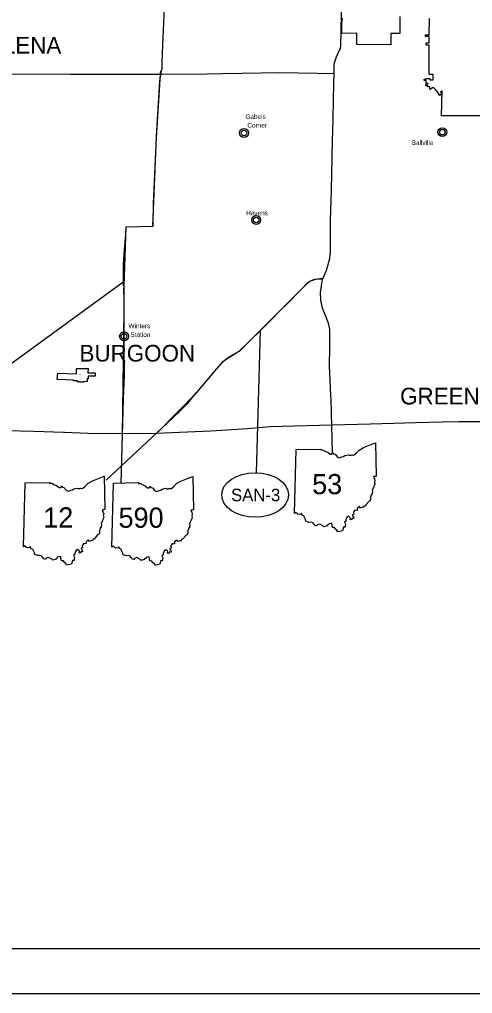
# Model space of a CAD drawing. Extents: x 0 to 798, y 0 to 440.
# Drawn here: x 266.6 to 368.1, y 0 to 218.5 of the extents above; entities that cross this region are included whole.
import ezdxf

# ---------------------------------------------------------------- set-up
doc = ezdxf.new("R2010")
doc.units = 0
for name, color, linetype in [('DV_X_Corp_Line', 7, 'Continuous'), ('GM_X_Corporation_Text', 7, 'Continuous'), ('GM_X_County', 7, 'Continuous'), ('GM_X_Rail_Line', 7, 'Continuous'), ('GM_X_State_Route', 7, 'Continuous'), ('GM_X_US_Route', 7, 'Continuous'), ('PV_P_Text', 7, 'Continuous'), ('SH_Border', 7, 'Continuous'), ('SH_Cut_Line', 7, 'Continuous'), ('SH_Data', 7, 'Continuous'), ('SH_Text', 7, 'Continuous')]:
    doc.layers.add(name, color=color, linetype=linetype)

msp = doc.modelspace()

# ---------------------------------------------------------------- linework, layer by layer
at = {"layer": 'DV_X_Corp_Line'}
for points in [[(351.89, 219.21), (351.83, 215.37), (349.85, 215.38), (349.85, 212.82), (342.22, 212.93), (342.22, 215.43), (338.88, 215.38), (338.88, 217.79), (338.97, 218.79)], [(376.75, 196.87), (366.34, 196.86), (361.22, 196.9), (361.38, 202.52), (360.99, 202.18), (361.27, 201.86), (360.83, 201.46), (360.54, 201.8), (360.61, 201.87), (360.16, 202.41), (359.75, 202.9), (359.44, 203.28), (359.36, 203.3), (359.36, 203.25), (358.57, 202.79), (358.57, 203.37), (358.17, 203.36), (358.17, 203.65), (357.72, 203.64), (357.73, 204.02), (358.21, 204.04), (358.21, 204.17), (357.74, 204.16), (357.75, 204.78), (357.3, 204.79), (357.3, 205.13), (357.76, 205.12), (357.76, 205.25), (358.56, 205.25), (358.57, 204.95), (359.31, 204.96), (359.3, 206.14), (358.45, 206.17), (358.44, 212.72), (357.78, 212.72), (357.78, 213.24), (358.44, 213.24), (358.44, 214.67), (357.62, 214.67), (357.62, 215.07), (358.45, 215.07), (358.48, 218.73)]]:
    msp.add_lwpolyline(points, dxfattribs=at)
msp.add_lwpolyline([(275.17, 139.19), (279.4, 139.03), (279.4, 140.22), (281.95, 140.21), (281.94, 139.27), (283.58, 139.23), (283.56, 138.47), (282.01, 138.5), (282.01, 137.92), (281.78, 137.92), (281.77, 137.24), (280.91, 137.27), (280.92, 137.12), (280.01, 137.14), (280.01, 137.24), (279.59, 137.25), (279.59, 137.43), (278.72, 137.46), (278.71, 137.62), (275.06, 137.72)], close=True, dxfattribs=at)
for centre, radius in [((316.92, 193.04), 0.982), ((316.92, 193.04), 0.623), ((361.39, 193.22), 0.982), ((361.39, 193.22), 0.623), ((319.64, 173.52), 0.982), ((319.64, 173.52), 0.623), ((290.03, 147.43), 0.982), ((290.03, 147.43), 0.623)]:
    msp.add_circle(centre, radius, dxfattribs=at)
at = {"layer": 'GM_X_County'}
msp.add_lwpolyline([(371.53, 128.26), (365.1, 128.22), (361.36, 128.16), (355.34, 128.01), (350.47, 127.86), (345.25, 127.7), (336.59, 127.48), (322.74, 127.1), (317.71, 126.66), (311.9, 126.27), (309.5, 126.13), (297.21, 125.6), (289.69, 125.53), (281.92, 125.62), (276.69, 125.82), (276.46, 125.82), (269.81, 126.07), (263.62, 126.19)], dxfattribs=at)
at = {"layer": 'GM_X_Rail_Line'}
msp.add_lwpolyline([(280.17, 138.87), (280.15, 138.93)], dxfattribs=at)
at = {"layer": 'GM_X_State_Route'}
for points in [[(298.6, 208.69), (298.59, 208.92), (298.76, 212.81), (298.99, 219.43), (299.23, 225.95), (299.47, 232.59), (299.71, 239.18), (300.21, 252.46), (300.21, 252.59)], [(298.19, 206.38), (298.23, 206.64), (298.31, 206.82), (298.45, 207.13), (298.59, 207.47), (298.61, 207.68), (298.6, 208.69)], [(290.12, 138.69), (290.06, 145.16), (290.08, 149.59), (290.07, 152.09), (290.05, 155.62), (290.01, 158), (290.02, 158.52), (290.02, 158.65), (290, 158.71), (289.92, 158.75), (289.93, 161.49), (289.92, 163.48), (290.13, 166.9), (290.4, 170.25), (290.52, 172.02), (296.56, 172.16), (296.64, 177.24), (296.85, 182.12), (297.23, 190.37), (297.31, 192.06), (298.17, 206.25), (298.19, 206.38)], [(336.9, 196.19), (336.91, 196.38), (337.07, 204.29), (337.13, 206.38)], [(336.78, 191.43), (336.83, 193.42), (336.9, 196.19), (336.9, 196.19)], [(335.31, 162.01), (335.4, 162.23), (336.15, 164.88), (336.25, 165.75), (336.28, 165.95), (336.28, 166.97), (336.29, 171.39), (336.34, 173.5), (336.5, 180.16), (336.78, 191.43), (336.78, 191.43)], [(334.58, 160.34), (335.31, 162.01)], [(314.86, 143.53), (315.2, 143.73), (315.67, 144), (316.04, 144.24), (322.79, 150.94), (325.42, 153.58), (326.42, 154.58), (329.83, 158), (331.24, 159.5), (331.49, 159.66), (331.83, 159.85), (332.19, 160.01), (332.43, 160.1)], [(332.43, 160.1), (332.56, 160.14), (333.05, 160.26), (333.4, 160.3), (334.58, 160.34)], [(334.38, 159.41), (334.42, 159.7), (334.58, 160.34)], [(336.74, 121.42), (336.46, 133.25), (336.41, 134.16), (336.12, 140.79), (336.17, 144.93), (336.13, 149.06), (335.83, 150.35), (335.72, 150.79), (334.55, 153.75), (334.16, 155.43), (334.07, 157.33), (334.26, 158.6)], [(334.26, 158.6), (334.38, 159.41)], [(306.35, 134.87), (306.35, 134.87), (307.02, 135.66), (309.28, 138.3), (310.17, 139.37), (311.4, 140.83), (312.14, 141.71), (312.87, 142.34), (314.86, 143.53), (314.86, 143.53)], [(289.41, 114.38), (289.89, 133.47), (290.12, 138.69)], [(304.9, 133.17), (304.91, 133.17), (306.35, 134.87)], [(286.02, 115.16), (299.7, 127.92), (302.36, 130.48), (303.52, 131.6), (303.99, 132.12), (304.31, 132.47), (304.9, 133.17)]]:
    msp.add_lwpolyline(points, dxfattribs=at)
at = {"layer": 'GM_X_US_Route'}
for points in [[(338.69, 215.45), (338.78, 220.46), (338.8, 221.88), (338.81, 222.12), (338.91, 222.56), (339.02, 222.9), (339.12, 223.18), (339.36, 223.69), (339.81, 224.46), (340.92, 226.41), (341.2, 226.85)], [(337.68, 210.11), (338.43, 211.78), (338.55, 212.03), (338.59, 212.11), (338.64, 212.55), (338.65, 212.94), (338.69, 215.41), (338.69, 215.45)], [(337.13, 206.38), (337.16, 207.08), (337.17, 208.08), (337.24, 208.77), (337.48, 209.68), (337.67, 210.1), (337.68, 210.11)], [(264.97, 206.33), (277.99, 206.24), (282.04, 206.26), (287.96, 206.21)], [(287.96, 206.21), (288.09, 206.21), (297.91, 206.24)], [(297.91, 206.24), (298.17, 206.25), (298.53, 206.24), (308.63, 206.3), (312.16, 206.41), (320.72, 206.57), (324.87, 206.64), (333.34, 206.47), (337.13, 206.38)]]:
    msp.add_lwpolyline(points, dxfattribs=at)
at = {"layer": 'PV_P_Text'}
for p, q in [((328.24, 107.67), (328.64, 122.04)), ((328.24, 107.67), (328.64, 122.04)), ((267.46, 100.2), (267.86, 114.56)), ((267.46, 100.2), (267.86, 114.56)), ((287.29, 100.14), (287.69, 114.5)), ((287.29, 100.14), (287.69, 114.5))]:
    msp.add_line(p, q, dxfattribs=at)
for points in [[(328.64, 122.04), (334.21, 122.13), (334.13, 121.96), (334.65, 121.92), (335.21, 121.61), (335.68, 121.42), (336.26, 120.96), (336.61, 120.97), (336.75, 121.34), (337.02, 121.05), (337.33, 121), (337.87, 120.31), (338.32, 120.17), (338.86, 120.4), (339.26, 120.44), (339.56, 120.67), (340.32, 120.87), (340.53, 120.75), (340.94, 120.78), (341.14, 120.86), (341.5, 120.79), (342.12, 121.31), (342.76, 121.92), (343.74, 122.51), (345.21, 123.06), (346.37, 123.55), (346.54, 116.09)], [(328.64, 122.04), (334.21, 122.13), (334.13, 121.96), (334.65, 121.92), (335.21, 121.61), (335.68, 121.42), (336.26, 120.96), (336.61, 120.97), (336.75, 121.34), (337.02, 121.05), (337.33, 121), (337.87, 120.31), (338.32, 120.17), (338.86, 120.4), (339.26, 120.44), (339.56, 120.67), (340.32, 120.87), (340.53, 120.75), (340.94, 120.78), (341.14, 120.86), (341.5, 120.79), (342.12, 121.31), (342.76, 121.92), (343.74, 122.51), (345.21, 123.06), (346.37, 123.55), (346.54, 116.09)], [(267.86, 114.56), (273.44, 114.66), (273.35, 114.48), (273.87, 114.45), (274.43, 114.14), (274.91, 113.95), (275.48, 113.49), (275.83, 113.5), (275.98, 113.87), (276.24, 113.58), (276.55, 113.53), (277.1, 112.84), (277.55, 112.69), (278.08, 112.93), (278.48, 112.97), (278.78, 113.2), (279.54, 113.4), (279.76, 113.28), (280.16, 113.3), (280.36, 113.39), (280.72, 113.31), (281.34, 113.84), (281.98, 114.45), (282.96, 115.03), (284.43, 115.58), (285.6, 116.08), (285.76, 108.62)], [(267.86, 114.56), (273.44, 114.66), (273.35, 114.48), (273.87, 114.45), (274.43, 114.14), (274.91, 113.95), (275.48, 113.49), (275.83, 113.5), (275.98, 113.87), (276.24, 113.58), (276.55, 113.53), (277.1, 112.84), (277.55, 112.69), (278.08, 112.93), (278.48, 112.97), (278.78, 113.2), (279.54, 113.4), (279.76, 113.28), (280.16, 113.3), (280.36, 113.39), (280.72, 113.31), (281.34, 113.84), (281.98, 114.45), (282.96, 115.03), (284.43, 115.58), (285.6, 116.08), (285.76, 108.62)], [(287.69, 114.5), (293.26, 114.6), (293.18, 114.42), (293.7, 114.39), (294.26, 114.08), (294.73, 113.89), (295.31, 113.43), (295.66, 113.43), (295.8, 113.81), (296.07, 113.52), (296.38, 113.47), (296.92, 112.78), (297.37, 112.63), (297.91, 112.87), (298.31, 112.91), (298.61, 113.14), (299.37, 113.34), (299.58, 113.22), (299.99, 113.24), (300.19, 113.33), (300.55, 113.25), (301.17, 113.77), (301.81, 114.39), (302.79, 114.97), (304.26, 115.52), (305.42, 116.01), (305.59, 108.56)], [(287.69, 114.5), (293.26, 114.6), (293.18, 114.42), (293.7, 114.39), (294.26, 114.08), (294.73, 113.89), (295.31, 113.43), (295.66, 113.43), (295.8, 113.81), (296.07, 113.52), (296.38, 113.47), (296.92, 112.78), (297.37, 112.63), (297.91, 112.87), (298.31, 112.91), (298.61, 113.14), (299.37, 113.34), (299.58, 113.22), (299.99, 113.24), (300.19, 113.33), (300.55, 113.25), (301.17, 113.77), (301.81, 114.39), (302.79, 114.97), (304.26, 115.52), (305.42, 116.01), (305.59, 108.56)], [(346.54, 116.09), (346.37, 115.99), (346.1, 116.04), (345.92, 115.83), (346.15, 115.48), (346.25, 115.11), (346.16, 114.71), (346.25, 114.37), (346.19, 114.09), (346.02, 113.81), (345.96, 113.55), (345.82, 113.27), (345.83, 113.11), (345.69, 112.98), (345.72, 112.52), (345.65, 112.26), (345.67, 112.04), (345.45, 111.98), (345.5, 111.79), (345.36, 111.65), (345.39, 111.41), (345.23, 111.25), (345.39, 110.94), (345.26, 110.84), (345.16, 110.46), (344.88, 110.38), (344.31, 109.69), (344.11, 109.42), (343.89, 109.36), (343.76, 109.09), (343.49, 109.09), (343.07, 108.9), (342.8, 109.22), (342.32, 108.83), (342.27, 108.39), (341.67, 108.4), (341.69, 108.17), (341.56, 108.11), (341.44, 107.88), (341.51, 107.48), (341.23, 107.38), (341.26, 107.14), (341.44, 107), (341.52, 106.55), (341.22, 106.64), (340.98, 106.27), (340.73, 106.35), (340.81, 106.67), (340.38, 107.06), (339.98, 106.75), (339.77, 106.26), (339.77, 105.93), (339.47, 105.73), (339.66, 105.26), (339.63, 104.94), (339.63, 104.63), (339.26, 104.64), (339.03, 103.82)], [(346.54, 116.09), (346.37, 115.99), (346.1, 116.04), (345.92, 115.83), (346.15, 115.48), (346.25, 115.11), (346.16, 114.71), (346.25, 114.37), (346.19, 114.09), (346.02, 113.81), (345.96, 113.55), (345.82, 113.27), (345.83, 113.11), (345.69, 112.98), (345.72, 112.52), (345.65, 112.26), (345.67, 112.04), (345.45, 111.98), (345.5, 111.79), (345.36, 111.65), (345.39, 111.41), (345.23, 111.25), (345.39, 110.94), (345.26, 110.84), (345.16, 110.46), (344.88, 110.38), (344.31, 109.69), (344.11, 109.42), (343.89, 109.36), (343.76, 109.09), (343.49, 109.09), (343.07, 108.9), (342.8, 109.22), (342.32, 108.83), (342.27, 108.39), (341.67, 108.4), (341.69, 108.17), (341.56, 108.11), (341.44, 107.88), (341.51, 107.48), (341.23, 107.38), (341.26, 107.14), (341.44, 107), (341.52, 106.55), (341.22, 106.64), (340.98, 106.27), (340.73, 106.35), (340.81, 106.67), (340.38, 107.06), (339.98, 106.75), (339.77, 106.26), (339.77, 105.93), (339.47, 105.73), (339.66, 105.26), (339.63, 104.94), (339.63, 104.63), (339.26, 104.64), (339.03, 103.82)], [(285.76, 108.62), (285.59, 108.52), (285.33, 108.57), (285.15, 108.36), (285.37, 108.01), (285.47, 107.64), (285.38, 107.23), (285.47, 106.9), (285.41, 106.62), (285.24, 106.34), (285.18, 106.07), (285.04, 105.79), (285.05, 105.64), (284.92, 105.51), (284.94, 105.05), (284.87, 104.79), (284.9, 104.57), (284.68, 104.51), (284.73, 104.32), (284.59, 104.18), (284.62, 103.94), (284.46, 103.78), (284.61, 103.47), (284.49, 103.37), (284.38, 102.99), (284.1, 102.91), (283.53, 102.21), (283.33, 101.95), (283.11, 101.89), (282.99, 101.62), (282.71, 101.62), (282.29, 101.43), (282.02, 101.75), (281.55, 101.36), (281.49, 100.91), (280.89, 100.93), (280.91, 100.7), (280.78, 100.64), (280.66, 100.41), (280.73, 100.01), (280.45, 99.9), (280.48, 99.67), (280.66, 99.53), (280.74, 99.08), (280.44, 99.17), (280.2, 98.79), (279.95, 98.88), (280.03, 99.2), (279.61, 99.58), (279.21, 99.28), (279, 98.79), (278.99, 98.46), (278.69, 98.26), (278.89, 97.79), (278.85, 97.47), (278.86, 97.16), (278.48, 97.17), (278.26, 96.35)], [(285.76, 108.62), (285.59, 108.52), (285.33, 108.57), (285.15, 108.36), (285.37, 108.01), (285.47, 107.64), (285.38, 107.23), (285.47, 106.9), (285.41, 106.62), (285.24, 106.34), (285.18, 106.07), (285.04, 105.79), (285.05, 105.64), (284.92, 105.51), (284.94, 105.05), (284.87, 104.79), (284.9, 104.57), (284.68, 104.51), (284.73, 104.32), (284.59, 104.18), (284.62, 103.94), (284.46, 103.78), (284.61, 103.47), (284.49, 103.37), (284.38, 102.99), (284.1, 102.91), (283.53, 102.21), (283.33, 101.95), (283.11, 101.89), (282.99, 101.62), (282.71, 101.62), (282.29, 101.43), (282.02, 101.75), (281.55, 101.36), (281.49, 100.91), (280.89, 100.93), (280.91, 100.7), (280.78, 100.64), (280.66, 100.41), (280.73, 100.01), (280.45, 99.9), (280.48, 99.67), (280.66, 99.53), (280.74, 99.08), (280.44, 99.17), (280.2, 98.79), (279.95, 98.88), (280.03, 99.2), (279.61, 99.58), (279.21, 99.28), (279, 98.79), (278.99, 98.46), (278.69, 98.26), (278.89, 97.79), (278.85, 97.47), (278.86, 97.16), (278.48, 97.17), (278.26, 96.35)], [(305.59, 108.56), (305.42, 108.46), (305.15, 108.5), (304.97, 108.3), (305.2, 107.95), (305.3, 107.58), (305.21, 107.17), (305.3, 106.84), (305.24, 106.56), (305.07, 106.28), (305.01, 106.01), (304.87, 105.73), (304.88, 105.57), (304.74, 105.45), (304.77, 104.98), (304.7, 104.73), (304.72, 104.5), (304.5, 104.44), (304.55, 104.26), (304.41, 104.12), (304.44, 103.87), (304.28, 103.72), (304.44, 103.41), (304.31, 103.31), (304.21, 102.93), (303.93, 102.85), (303.36, 102.15), (303.16, 101.89), (302.94, 101.82), (302.81, 101.55), (302.54, 101.55), (302.12, 101.37), (301.85, 101.69), (301.37, 101.3), (301.32, 100.85), (300.72, 100.87), (300.74, 100.64), (300.61, 100.57), (300.49, 100.35), (300.56, 99.94), (300.28, 99.84), (300.31, 99.61), (300.49, 99.46), (300.57, 99.02), (300.27, 99.11), (300.03, 98.73), (299.78, 98.82), (299.86, 99.14), (299.43, 99.52), (299.03, 99.22), (298.82, 98.72), (298.82, 98.39), (298.52, 98.19), (298.71, 97.73), (298.68, 97.4), (298.68, 97.1), (298.31, 97.11), (298.08, 96.29)], [(305.59, 108.56), (305.42, 108.46), (305.15, 108.5), (304.97, 108.3), (305.2, 107.95), (305.3, 107.58), (305.21, 107.17), (305.3, 106.84), (305.24, 106.56), (305.07, 106.28), (305.01, 106.01), (304.87, 105.73), (304.88, 105.57), (304.74, 105.45), (304.77, 104.98), (304.7, 104.73), (304.72, 104.5), (304.5, 104.44), (304.55, 104.26), (304.41, 104.12), (304.44, 103.87), (304.28, 103.72), (304.44, 103.41), (304.31, 103.31), (304.21, 102.93), (303.93, 102.85), (303.36, 102.15), (303.16, 101.89), (302.94, 101.82), (302.81, 101.55), (302.54, 101.55), (302.12, 101.37), (301.85, 101.69), (301.37, 101.3), (301.32, 100.85), (300.72, 100.87), (300.74, 100.64), (300.61, 100.57), (300.49, 100.35), (300.56, 99.94), (300.28, 99.84), (300.31, 99.61), (300.49, 99.46), (300.57, 99.02), (300.27, 99.11), (300.03, 98.73), (299.78, 98.82), (299.86, 99.14), (299.43, 99.52), (299.03, 99.22), (298.82, 98.72), (298.82, 98.39), (298.52, 98.19), (298.71, 97.73), (298.68, 97.4), (298.68, 97.1), (298.31, 97.11), (298.08, 96.29)], [(339.03, 103.82), (338.38, 103.66), (337.93, 103.57), (337.77, 103.94), (337.45, 104.14), (337.24, 104.52), (336.78, 104.57), (336.67, 105.09), (336.61, 105.51), (335.98, 105.4), (335.81, 105.15), (335.58, 105.08), (335.45, 104.82), (335.14, 104.8), (334.82, 104.67), (334.6, 104.93), (334.06, 105.18), (333.82, 105.31), (333.31, 105.11), (333.21, 104.87), (332.8, 104.97), (332.71, 105.24), (332.46, 105.33), (332.41, 105.61), (331.89, 105.76), (331.49, 105.7), (330.79, 105.93), (330.74, 106.31), (330.5, 106.77), (330.38, 107.09), (329.93, 107.33), (329.84, 107.71), (329.7, 107.7), (329.57, 107.54), (329.08, 107.47), (328.88, 107.63), (328.6, 107.89), (328.24, 107.67)], [(339.03, 103.82), (338.38, 103.66), (337.93, 103.57), (337.77, 103.94), (337.45, 104.14), (337.24, 104.52), (336.78, 104.57), (336.67, 105.09), (336.61, 105.51), (335.98, 105.4), (335.81, 105.15), (335.58, 105.08), (335.45, 104.82), (335.14, 104.8), (334.82, 104.67), (334.6, 104.93), (334.06, 105.18), (333.82, 105.31), (333.31, 105.11), (333.21, 104.87), (332.8, 104.97), (332.71, 105.24), (332.46, 105.33), (332.41, 105.61), (331.89, 105.76), (331.49, 105.7), (330.79, 105.93), (330.74, 106.31), (330.5, 106.77), (330.38, 107.09), (329.93, 107.33), (329.84, 107.71), (329.7, 107.7), (329.57, 107.54), (329.08, 107.47), (328.88, 107.63), (328.6, 107.89), (328.24, 107.67)], [(278.26, 96.35), (277.61, 96.19), (277.15, 96.1), (277, 96.47), (276.67, 96.67), (276.46, 97.04), (276, 97.1), (275.89, 97.61), (275.84, 98.03), (275.2, 97.93), (275.03, 97.67), (274.8, 97.6), (274.67, 97.35), (274.37, 97.32), (274.04, 97.2), (273.82, 97.46), (273.28, 97.71), (273.04, 97.84), (272.54, 97.64), (272.43, 97.4), (272.02, 97.5), (271.93, 97.77), (271.69, 97.85), (271.63, 98.14), (271.11, 98.29), (270.71, 98.23), (270.01, 98.46), (269.97, 98.84), (269.73, 99.3), (269.6, 99.61), (269.16, 99.86), (269.07, 100.24), (268.92, 100.23), (268.79, 100.07), (268.3, 100), (268.1, 100.16), (267.83, 100.42), (267.46, 100.2)], [(278.26, 96.35), (277.61, 96.19), (277.15, 96.1), (277, 96.47), (276.67, 96.67), (276.46, 97.04), (276, 97.1), (275.89, 97.61), (275.84, 98.03), (275.2, 97.93), (275.03, 97.67), (274.8, 97.6), (274.67, 97.35), (274.37, 97.32), (274.04, 97.2), (273.82, 97.46), (273.28, 97.71), (273.04, 97.84), (272.54, 97.64), (272.43, 97.4), (272.02, 97.5), (271.93, 97.77), (271.69, 97.85), (271.63, 98.14), (271.11, 98.29), (270.71, 98.23), (270.01, 98.46), (269.97, 98.84), (269.73, 99.3), (269.6, 99.61), (269.16, 99.86), (269.07, 100.24), (268.92, 100.23), (268.79, 100.07), (268.3, 100), (268.1, 100.16), (267.83, 100.42), (267.46, 100.2)], [(298.08, 96.29), (297.43, 96.13), (296.98, 96.03), (296.82, 96.41), (296.5, 96.61), (296.29, 96.98), (295.83, 97.03), (295.72, 97.55), (295.66, 97.97), (295.03, 97.87), (294.86, 97.61), (294.63, 97.54), (294.5, 97.28), (294.19, 97.26), (293.87, 97.14), (293.65, 97.39), (293.11, 97.65), (292.87, 97.78), (292.36, 97.58), (292.26, 97.33), (291.85, 97.44), (291.76, 97.71), (291.51, 97.79), (291.46, 98.08), (290.94, 98.23), (290.54, 98.17), (289.84, 98.4), (289.79, 98.78), (289.55, 99.23), (289.43, 99.55), (288.98, 99.8), (288.89, 100.17), (288.75, 100.16), (288.62, 100.01), (288.13, 99.94), (287.93, 100.09), (287.65, 100.36), (287.29, 100.14)], [(298.08, 96.29), (297.43, 96.13), (296.98, 96.03), (296.82, 96.41), (296.5, 96.61), (296.29, 96.98), (295.83, 97.03), (295.72, 97.55), (295.66, 97.97), (295.03, 97.87), (294.86, 97.61), (294.63, 97.54), (294.5, 97.28), (294.19, 97.26), (293.87, 97.14), (293.65, 97.39), (293.11, 97.65), (292.87, 97.78), (292.36, 97.58), (292.26, 97.33), (291.85, 97.44), (291.76, 97.71), (291.51, 97.79), (291.46, 98.08), (290.94, 98.23), (290.54, 98.17), (289.84, 98.4), (289.79, 98.78), (289.55, 99.23), (289.43, 99.55), (288.98, 99.8), (288.89, 100.17), (288.75, 100.16), (288.62, 100.01), (288.13, 99.94), (287.93, 100.09), (287.65, 100.36), (287.29, 100.14)]]:
    msp.add_lwpolyline(points, dxfattribs=at)
at = {"layer": 'SH_Border'}
msp.add_lwpolyline([(30, 430), (670, 430), (670, 10), (30, 10)], close=True, dxfattribs=at)
at = {"layer": 'SH_Cut_Line'}
msp.add_lwpolyline([(0, 0), (680, 0), (680, 440), (0, 440)], close=True, dxfattribs=at)
at = {"layer": 'SH_Data'}
for p, q in [((229.11, 115.35), (290.07, 159.81)), ((319.72, 116.84), (320.59, 148.77))]:
    msp.add_line(p, q, dxfattribs=at)
msp.add_ellipse((319.42, 111.84), major_axis=(7.5, 0), ratio=0.666667, dxfattribs=at)
at = {"layer": 'SH_Text'}
for points in [[(289.68, 125.25), (290.06, 153.28), (290.02, 158.65), (290.52, 172.02), (296.48, 172.16), (297.32, 192.25), (298.08, 204.66), (298.43, 207.09)], [(297.76, 126.11), (306.33, 134.85), (310.28, 139.5), (312.29, 141.83), (313.62, 142.79), (315.81, 144.09), (318.2, 146.38), (329.1, 157.27), (331.54, 159.69), (332.96, 160.24), (334.63, 160.46)]]:
    msp.add_lwpolyline(points, dxfattribs=at)

# ---------------------------------------------------------------- texts
at = {"layer": 'DV_X_Corp_Line'}
for s, p in [('Gabels', (317.24, 196.19)), ('Corner', (317.68, 194.24)), ('Ballville', (354.51, 190.35)), ('Havens', (317.39, 174.57)), ('Winters', (291.03, 149.25)), ('Station', (291.46, 147.3))]:
    msp.add_text(s, height=1.042, rotation=0, dxfattribs=at).set_placement(p)
at = {"layer": 'GM_X_Corporation_Text'}
for s, p in [('HELENA', (255.9, 210.84)), ('BURGOON', (280.05, 141.76)), ('GREEN SPRINGS', (351.92, 132.14))]:
    msp.add_text(s, height=3.75, rotation=0, dxfattribs=at).set_placement(p)
at = {"layer": 'PV_P_Text'}
for s, p in [('53', (332.2, 112.01)), ('12', (271.91, 104.54)), ('590', (288.79, 104.48))]:
    msp.add_text(s, height=4.528, dxfattribs=at).set_placement(p)
at = {"layer": 'SH_Data'}
msp.add_text('SAN-3', height=2.8, dxfattribs=at).set_placement((314.02, 110.44))

doc.saveas('drawing.dxf')
